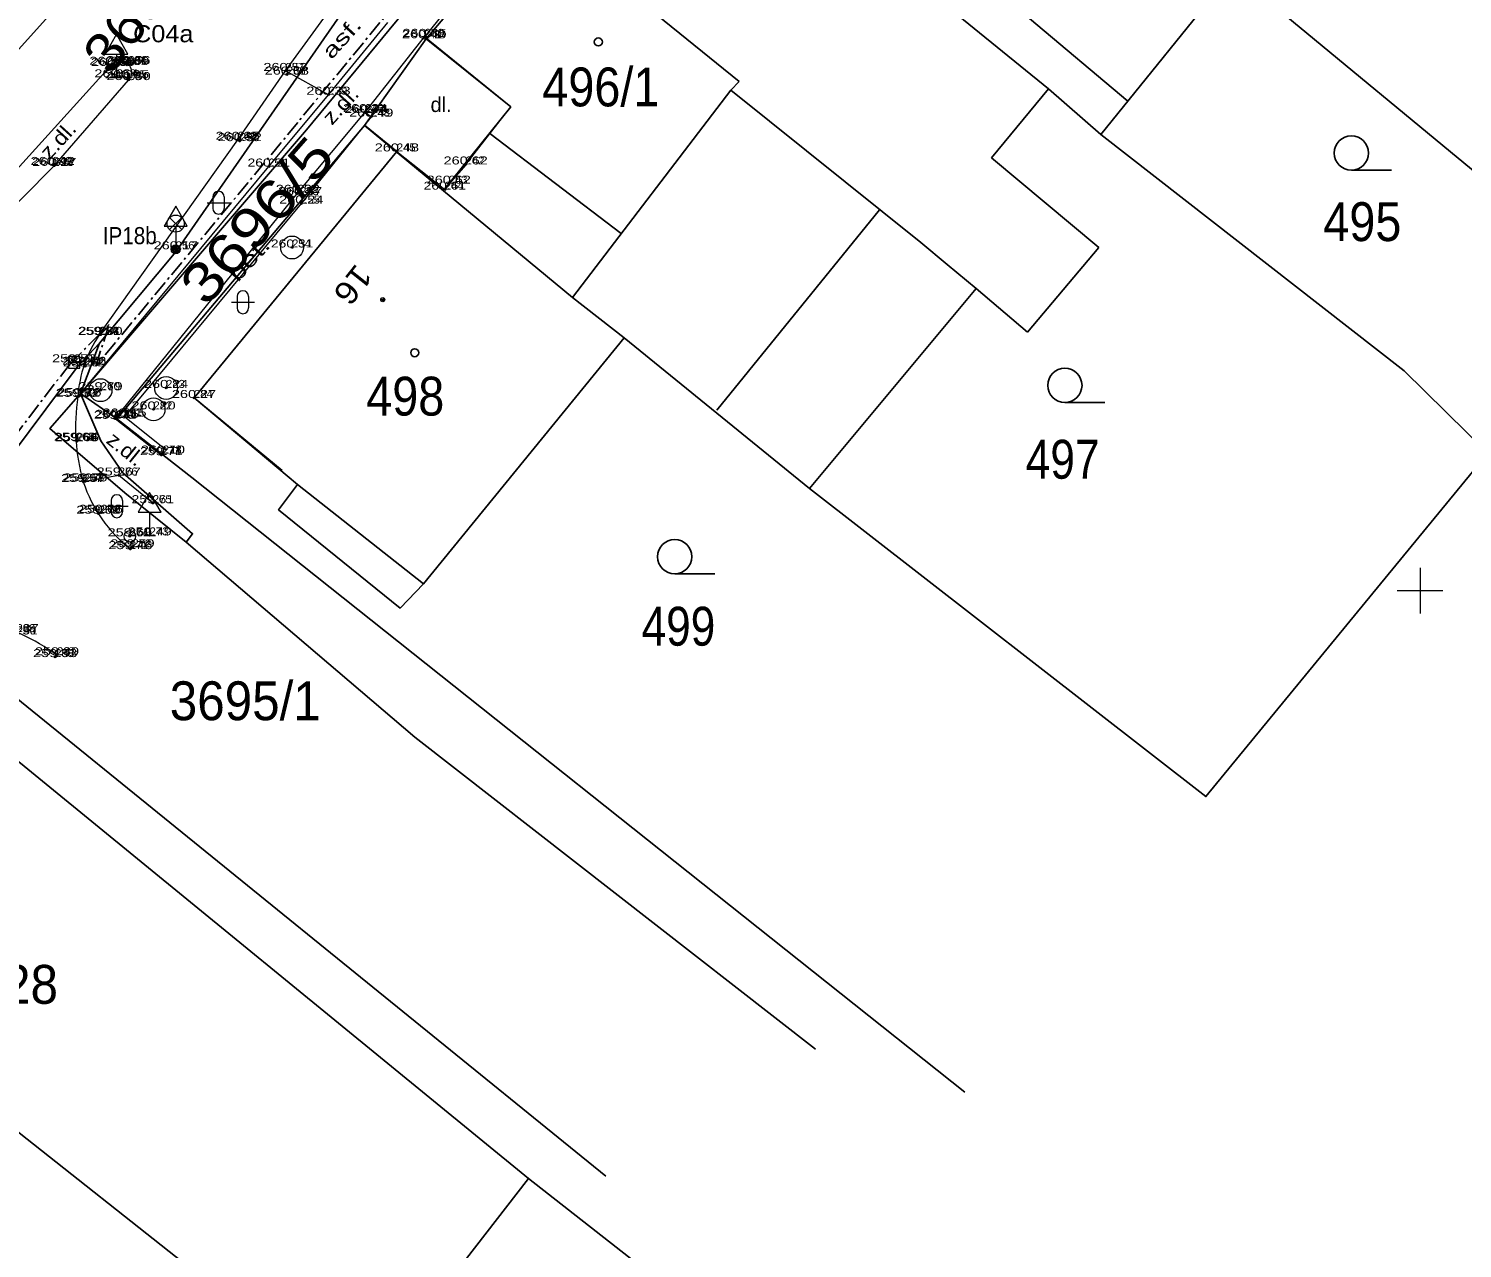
# Model space of a CAD drawing. Extents: x -568530 to -568223, y -1154101 to -1153740.
# Drawn here: x -568460.8 to -568398.2, y -1154028.8 to -1153975.4 of the extents above; entities that cross this region are included whole.
import ezdxf
from ezdxf.enums import TextEntityAlignment as Align

# ---------------------------------------------------------------- set-up
doc = ezdxf.new("R2010")
doc.units = 0
doc.header["$LTSCALE"] = 0.14
doc.header["$PDMODE"] = 32
doc.header["$PDSIZE"] = 0.07
doc.linetypes.add('DOT_DASHED', pattern=[7.7, 5, -1.2, 0.3, -1.2])
for name, color, linetype, lineweight in [('1', 7, 'Continuous', 25), ('10', 7, 'Continuous', 13), ('11', 7, 'Continuous', 13), ('12', 7, 'Continuous', 13), ('25', 7, 'Continuous', 13), ('27', 7, 'Continuous', 13), ('28', 7, 'Continuous', 13), ('33', 7, 'Continuous', 13), ('34', 7, 'Continuous', 13), ('36', 7, 'Continuous', 13), ('39', 7, 'Continuous', 13), ('4', 7, 'Continuous', 25), ('42', 7, 'Continuous', 13), ('5', 7, 'Continuous', 13), ('6', 7, 'DOT_DASHED', 25), ('61', 7, 'Continuous', 13)]:
    doc.layers.add(name, color=color, linetype=linetype, lineweight=lineweight)
for name, color, linetype in [('13', 7, 'Continuous'), ('18', 7, 'Continuous'), ('19', 7, 'Continuous'), ('40', 7, 'Continuous'), ('47', 7, 'Continuous')]:
    doc.layers.add(name, color=color, linetype=linetype)

msp = doc.modelspace()

# ---------------------------------------------------------------- linework, layer by layer
at = {"layer": '1'}
for p, q in [((-568443.46, -1153975.87), (-568433.42, -1153964.08)), ((-568438.82, -1153970.42), (-568429.77, -1153977.74)), ((-568408.2, -1153972.93), (-568390.78, -1153987.34)), ((-568418.74, -1153981.08), (-568416.24, -1153978.06)), ((-568413.96, -1153980.06), (-568400.7, -1153990.39)), ((-568414.04, -1153985), (-568418.74, -1153981.08)), ((-568421.83, -1153984.78), (-568420.68, -1153985.74)), ((-568417.17, -1153988.7), (-568414.04, -1153985)), ((-568420.68, -1153985.74), (-568419.41, -1153986.8)), ((-568419.41, -1153986.8), (-568417.17, -1153988.7)), ((-568457.74, -1153989.19), (-568458.68, -1153990.17)), ((-568457.74, -1153989.19), (-568458.57, -1153991.38)), ((-568458.68, -1153990.17), (-568467.98, -1154002.62)), ((-568465.85, -1154003.75), (-568438.98, -1154025.71)), ((-568474.11, -1154013.58), (-568446.48, -1154035.38))]:
    msp.add_line(p, q, dxfattribs=at)
for points in [[(-568416.35, -1153942.92), (-568421.22, -1153939.56), (-568427.43, -1153948.41), (-568440.04, -1153964.5), (-568454.41, -1153985.19), (-568457.74, -1153989.19)], [(-568421.83, -1153950.13), (-568427.7, -1153957.09), (-568433.42, -1153964.08), (-568426, -1153970.14), (-568416.24, -1153978.06), (-568413.96, -1153980.06), (-568408.2, -1153972.93), (-568413.31, -1153968.6), (-568420.22, -1153963.08), (-568427.7, -1153957.09)], [(-568436.57, -1153965.56), (-568442.92, -1153972.86), (-568448.69, -1153979.85), (-568458.57, -1153991.38), (-568456.99, -1153992.49)], [(-568419.41, -1153986.8), (-568426.69, -1153995.54), (-568434.8, -1153988.95), (-568437.06, -1153987.18), (-568446.16, -1153979.66), (-568443.46, -1153975.87)], [(-568429.77, -1153977.74), (-568430.14, -1153978.12), (-568421.83, -1153984.78)], [(-568446.16, -1153979.66), (-568456.99, -1153992.49), (-568453.71, -1153995.05), (-568419.9, -1154021.94)], [(-568449.08, -1153995.36), (-568453.61, -1153991.58), (-568444.74, -1153980.8)], [(-568449.08, -1153995.36), (-568449.91, -1153996.47), (-568444.59, -1154000.77), (-568443.57, -1153999.71), (-568434.8, -1153988.95)], [(-568426.69, -1153995.54), (-568409.36, -1154009.01), (-568397.04, -1153994), (-568400.7, -1153990.39)], [(-568458.52, -1154050.91), (-568438.98, -1154025.71), (-568434.27, -1154029.4)]]:
    msp.add_lwpolyline(points, dxfattribs=at)
at = {"layer": '10'}
for p, q in [((-568468.5, -1153984.3), (-568459.56, -1153974.44)), ((-568464.54, -1153985.09), (-568457.22, -1153977.01)), ((-568457.75, -1153988.82), (-568451.7, -1153980.29))]:
    msp.add_line(p, q, dxfattribs=at)
for points in [[(-568451.7, -1153980.29), (-568449.61, -1153977.28), (-568446.84, -1153973.45), (-568445.91, -1153972.15), (-568442.46, -1153967.27), (-568439.57, -1153963.38), (-568433.28, -1153955), (-568432.53, -1153954), (-568431.81, -1153953.03), (-568426.84, -1153946.5), (-568420.35, -1153937.98), (-568416.07, -1153932.32)], [(-568463.95, -1153985.68), (-568459.72, -1153981.43), (-568456.47, -1153977.68)]]:
    msp.add_lwpolyline(points, dxfattribs=at)
for centre, radius, start, end in [((-568456.8362, -1153977.3352), 0.503, 316.72145, 139.7276), ((-568453.3107, -1153991.8779), 5.3906, 145.44041, 176.30001), ((-568450.1568, -1153992.8472), 8.6342, 171.22484, 196.15793), ((-568452.5171, -1153993.2846), 6.25, 198.32832, 231.70802), ((-568464.9881, -1154010.2166), 9.1429, 53.8913, 76.66924)]:
    msp.add_arc(centre, radius, start, end, dxfattribs=at)
at = {"layer": '11'}
for p, q in [((-568446.13, -1153979.08), (-568443.53, -1153975.79)), ((-568447.73, -1153978.32), (-568449.61, -1153977.28)), ((-568444.74, -1153980.8), (-568446.162, -1153979.655))]:
    msp.add_line(p, q, dxfattribs=at)
for points in [[(-568458.69, -1153991.53), (-568450.34, -1153981.46), (-568447.73, -1153978.32), (-568445.13, -1153975.16)], [(-568455.04, -1153994.08), (-568457.06, -1153992.49), (-568449.07, -1153982.61), (-568446.13, -1153979.08), (-568445.86, -1153979.28)], [(-568445.86, -1153979.28), (-568446.162, -1153979.655), (-568448.92, -1153983.08)], [(-568448.92, -1153983.08), (-568456.65, -1153992.39), (-568454.82, -1153993.866)], [(-568455.41, -1153996.18), (-568456.9, -1153994.97), (-568458.45, -1153995.25)]]:
    msp.add_lwpolyline(points, dxfattribs=at)
for p in [(-568443.55, -1153975.85), (-568443.53, -1153975.79), (-568457.22, -1153977.01), (-568456.53, -1153977.02), (-568456.48, -1153976.98), (-568457.15, -1153977.06), (-568457, -1153977.56), (-568456.54, -1153977.6), (-568449.61, -1153977.28), (-568449.55, -1153977.44), (-568456.47, -1153977.68), (-568447.73, -1153978.32), (-568446.13, -1153979.08), (-568446.08, -1153979.12), (-568445.86, -1153979.28), (-568451.7, -1153980.29), (-568451.61, -1153980.35), (-568459.79, -1153981.39), (-568444.74, -1153980.8), (-568441.73, -1153981.37), (-568459.72, -1153981.43), (-568450.34, -1153981.46), (-568449.07, -1153982.61), (-568442.64, -1153982.47), (-568442.47, -1153982.21), (-568448.97, -1153982.71), (-568448.92, -1153983.08), (-568454.41, -1153985.08), (-568449.32, -1153985), (-568457.75, -1153988.82), (-568457.7, -1153988.82), (-568458.85, -1153990.02), (-568458.41, -1153990.13), (-568458.37, -1153990.2), (-568457.7, -1153991.24), (-568454.83, -1153991.14), (-568458.69, -1153991.53), (-568458.62, -1153991.5), (-568453.61, -1153991.58), (-568457.06, -1153992.49), (-568456.98, -1153992.45), (-568456.65, -1153992.39), (-568455.38, -1153992.08), (-568458.77, -1153993.45), (-568458.73, -1153993.47), (-568455.04, -1153994.08), (-568454.97, -1153994.01), (-568456.9, -1153994.97), (-568458.45, -1153995.25), (-568458.36, -1153995.23), (-568455.41, -1153996.18), (-568457.79, -1153996.64), (-568457.68, -1153996.6), (-568456.42, -1153997.63), (-568455.55, -1153997.59), (-568456.39, -1153998.19), (-568456.3, -1153998.11), (-568459.68, -1154002.91), (-568459.6, -1154002.83)]:
    msp.add_point(p, dxfattribs=at)
at = {"layer": '25', "lineweight": 25}
for p, q in [((-568403, -1153981.62), (-568401.25, -1153981.62)), ((-568415.53, -1153991.78), (-568413.78, -1153991.78)), ((-568432.59, -1153999.27), (-568430.84, -1153999.27))]:
    msp.add_line(p, q, dxfattribs=at)
for centre, radius in [((-568435.93, -1153976.01), 0.175), ((-568403, -1153980.87), 0.75), ((-568443.96, -1153989.6), 0.175), ((-568415.53, -1153991.03), 0.75), ((-568432.59, -1153998.52), 0.75)]:
    msp.add_circle(centre, radius, dxfattribs=at)
at = {"layer": '27'}
msp.add_line((-568459.1, -1153990.02), (-568458.6, -1153990.02), dxfattribs=at)
msp.add_lwpolyline([(-568459.1, -1153990.27), (-568458.6, -1153990.27), (-568458.6, -1153989.77), (-568459.1, -1153989.77)], close=True, dxfattribs=at)
for centre in [(-568449.32, -1153985), (-568457.7, -1153991.24), (-568454.83, -1153991.14), (-568455.38, -1153992.08)]:
    msp.add_circle(centre, 0.5, dxfattribs=at)
at = {"layer": '28'}
msp.add_circle((-568456.42, -1153997.63), 0.25, dxfattribs=at)
at = {"layer": '33'}
for p, q in [((-568454.675, -1153984.22), (-568454.145, -1153983.69)), ((-568454.675, -1153983.69), (-568454.145, -1153984.22)), ((-568454.41, -1153984.33), (-568454.41, -1153985.08))]:
    msp.add_line(p, q, dxfattribs=at)
for centre, radius in [((-568454.41, -1153983.955), 0.375), ((-568454.41, -1153985.08), 0.2), ((-568454.41, -1153985.08), 0.1445), ((-568454.41, -1153985.08), 0.0876)]:
    msp.add_circle(centre, radius, dxfattribs=at)
at = {"layer": '34'}
for p, q in [((-568457, -1153976.542), (-568457, -1153977.56)), ((-568457.25, -1153977.56), (-568456.75, -1153977.56)), ((-568454.41, -1153984.062), (-568454.41, -1153985.08)), ((-568455.55, -1153996.572), (-568455.55, -1153997.59)), ((-568455.8, -1153997.59), (-568455.3, -1153997.59))]:
    msp.add_line(p, q, dxfattribs=at)
for points in [[(-568457.5, -1153976.542), (-568456.5, -1153976.542), (-568457, -1153975.676)], [(-568454.91, -1153984.062), (-568453.91, -1153984.062), (-568454.41, -1153983.196)], [(-568456.05, -1153996.572), (-568455.05, -1153996.572), (-568455.55, -1153995.706)]]:
    msp.add_lwpolyline(points, close=True, dxfattribs=at)
at = {"layer": '36'}
for p, q in [((-568453.039, -1153983.04), (-568452.039, -1153983.04)), ((-568452.789, -1153982.79), (-568452.789, -1153983.29)), ((-568452.289, -1153982.79), (-568452.289, -1153983.29)), ((-568451.971, -1153987.394), (-568450.971, -1153987.394)), ((-568451.721, -1153987.144), (-568451.721, -1153987.644)), ((-568451.221, -1153987.144), (-568451.221, -1153987.644)), ((-568457.487, -1153996.313), (-568456.487, -1153996.313)), ((-568457.237, -1153996.063), (-568457.237, -1153996.563)), ((-568456.737, -1153996.063), (-568456.737, -1153996.563))]:
    msp.add_line(p, q, dxfattribs=at)
for centre, start, end in [((-568452.5384, -1153982.7905), 0, 180), ((-568452.5384, -1153983.2905), 180, 0), ((-568451.4705, -1153987.1447), 0, 180), ((-568451.4705, -1153987.6447), 180, 0), ((-568456.9863, -1153996.0637), 0, 180), ((-568456.9863, -1153996.5637), 180, 0)]:
    msp.add_arc(centre, 0.25, start, end, dxfattribs=at)
at = {"layer": '39'}
for radius in [0.09, 0.0398]:
    msp.add_circle((-568445.3578, -1153987.2827), radius, dxfattribs=at)
at = {"layer": '4'}
for p, q in [((-568437.06, -1153987.18), (-568430.14, -1153978.12)), ((-568440.68, -1153980.02), (-568434.93, -1153984.39)), ((-568430.75, -1153992.12), (-568423.64, -1153983.36)), ((-568457.68, -1153993.46), (-568458.57, -1153991.38)), ((-568443.57, -1153999.71), (-568449.08, -1153995.36)), ((-568453.95, -1153997.88), (-568443.95, -1154006.41)), ((-568462.84, -1154003.52), (-568435.6, -1154025.6)), ((-568443.95, -1154006.41), (-568426.44, -1154020.05))]:
    msp.add_line(p, q, dxfattribs=at)
for points in [[(-568424.44, -1153968.23), (-568416.69, -1153974.53), (-568417.07, -1153974.98), (-568412.78, -1153978.6)], [(-568443.46, -1153975.87), (-568439.76, -1153978.85), (-568442.71, -1153982.52)], [(-568453.95, -1153997.88), (-568456.63, -1153995.73), (-568459.92, -1153992.91), (-568458.57, -1153991.38)], [(-568453.95, -1153997.88), (-568453.67, -1153997.52), (-568456.72, -1153994.86), (-568457.68, -1153993.46)]]:
    msp.add_lwpolyline(points, dxfattribs=at)
at = {"layer": '5'}
for p, q in [((-568438.92, -1153970.1), (-568443.53, -1153975.79)), ((-568449.749, -1153994.757), (-568453.61, -1153991.58))]:
    msp.add_line(p, q, dxfattribs=at)
for points in [[(-568442.47, -1153982.21), (-568441.73, -1153981.37), (-568439.758, -1153978.846), (-568443.53, -1153975.79)], [(-568453.61, -1153991.58), (-568444.74, -1153980.8), (-568442.64, -1153982.47), (-568442.47, -1153982.21)]]:
    msp.add_lwpolyline(points, dxfattribs=at)
at = {"layer": '6'}
for p, q in [((-568443.31, -1153972.54), (-568449.08, -1153979.53)), ((-568449.07, -1153979.53), (-568457.91, -1153990.19)), ((-568459.03, -1153990.08), (-568457.32, -1153988.37)), ((-568457.91, -1153990.19), (-568457.32, -1153988.37)), ((-568459.03, -1153990.08), (-568468.38, -1154002.32))]:
    msp.add_line(p, q, dxfattribs=at)
at = {"layer": '6', "linetype": 'Continuous', "lineweight": 35}
msp.add_line((-568441.73, -1153981.37), (-568442.47, -1153982.21), dxfattribs=at)
at = {"layer": '61'}
for p, q in [((-568400, -1153999), (-568400, -1154001)), ((-568400, -1153999), (-568400, -1154001)), ((-568401, -1154000), (-568399, -1154000)), ((-568401, -1154000), (-568399, -1154000))]:
    msp.add_line(p, q, dxfattribs=at)

# ---------------------------------------------------------------- texts
at = {"layer": '12'}
for s, width, p in [('260.48', 1.35, (-568443.55, -1153975.85)), ('260.35', 1.35, (-568443.5305, -1153975.79)), ('260.55', 1.35, (-568457.2205, -1153977.01)), ('260.69', 1.35, (-568457.15, -1153977.06)), ('260.69', 1.35, (-568456.53, -1153977.02)), ('260.56', 1.35, (-568456.48, -1153976.98)), ('260.53', 1.35, (-568449.61, -1153977.28)), ('260.64', 1.35, (-568457, -1153977.56)), ('260.65', 1.35, (-568456.5405, -1153977.6)), ('260.50', 1.35, (-568456.4695, -1153977.68)), ('260.68', 1.35, (-568449.55, -1153977.44)), ('260.33', 1.35, (-568447.73, -1153978.32)), ('260.34', 1.35, (-568446.13, -1153979.08)), ('260.74', 1.35, (-568446.08, -1153979.12)), ('260.49', 1.35, (-568445.86, -1153979.28)), ('260.35', 1.35, (-568451.7005, -1153980.29)), ('260.52', 1.35, (-568451.61, -1153980.35)), ('260.48', 1.35, (-568444.74, -1153980.8)), ('260.42', 1.35, (-568459.79, -1153981.39)), ('260.27', 1.35, (-568459.72, -1153981.43)), ('260.21', 1.3, (-568450.34, -1153981.46)), ('260.62', 1.35, (-568441.73, -1153981.37)), ('260.62', 1.35, (-568442.47, -1153982.21)), ('260.22', 1.35, (-568449.07, -1153982.61)), ('260.57', 1.35, (-568448.97, -1153982.71)), ('260.61', 1.3, (-568442.64, -1153982.47)), ('260.24', 1.35, (-568448.92, -1153983.08)), ('260.17', 1.35, (-568454.41, -1153985.08)), ('260.31', 1.3, (-568449.32, -1153985)), ('259.81', 1.3, (-568457.75, -1153988.82)), ('259.90', 1.35, (-568457.6995, -1153988.82)), ('259.73', 1.35, (-568458.85, -1153990.02)), ('259.76', 1.35, (-568458.41, -1153990.13)), ('259.84', 1.35, (-568458.37, -1153990.2)), ('259.72', 1.35, (-568458.69, -1153991.53)), ('259.76', 1.35, (-568458.62, -1153991.5)), ('259.79', 1.35, (-568457.7, -1153991.24)), ('260.24', 1.35, (-568454.83, -1153991.14)), ('260.27', 1.35, (-568453.61, -1153991.58)), ('260.20', 1.35, (-568455.3795, -1153992.08)), ('259.71', 1.3, (-568457.06, -1153992.49)), ('260.15', 1.35, (-568456.9805, -1153992.45)), ('260.15', 1.35, (-568456.6505, -1153992.39)), ('259.64', 1.35, (-568458.77, -1153993.45)), ('259.66', 1.35, (-568458.73, -1153993.47)), ('259.71', 1.3, (-568455.04, -1153994.08)), ('260.10', 1.35, (-568454.9695, -1153994.01)), ('259.57', 1.35, (-568458.45, -1153995.25)), ('259.70', 1.35, (-568458.3595, -1153995.23)), ('259.67', 1.35, (-568456.9, -1153994.97)), ('259.52', 1.35, (-568457.79, -1153996.64)), ('259.66', 1.35, (-568457.68, -1153996.6)), ('259.61', 1.3, (-568455.41, -1153996.18)), ('259.60', 1.35, (-568456.4195, -1153997.63)), ('259.49', 1.35, (-568455.55, -1153997.59)), ('259.46', 1.35, (-568456.39, -1153998.19)), ('259.59', 1.35, (-568456.3, -1153998.11)), ('259.37', 1.35, (-568461.37, -1154001.82)), ('259.51', 1.3, (-568461.37, -1154001.92)), ('259.53', 1.35, (-568459.68, -1154002.91)), ('259.39', 1.35, (-568459.6, -1154002.83))]:
    msp.add_text(s, height=0.35, dxfattribs=dict(at, width=width)).set_placement(p, align=Align.CENTER)
at = {"layer": '13'}
for s, width, p in [('241', 0.95, (-568443.55, -1153975.85)), ('230', 1.1, (-568443.53, -1153975.79)), ('388', 1.05, (-568457.22, -1153977.01)), ('389', 1.05, (-568457.15, -1153977.06)), ('387', 1.05, (-568456.53, -1153977.02)), ('386', 1.05, (-568456.48, -1153976.98)), ('237', 1.05, (-568449.61, -1153977.28)), ('390', 1.1, (-568457, -1153977.56)), ('385', 1.05, (-568456.54, -1153977.6)), ('384', 1.05, (-568456.47, -1153977.68)), ('238', 1.05, (-568449.55, -1153977.44)), ('239', 1.05, (-568447.73, -1153978.32)), ('246', 1.05, (-568446.13, -1153979.08)), ('247', 1.05, (-568446.08, -1153979.12)), ('248', 1.05, (-568445.86, -1153979.28)), ('249', 1.05, (-568451.7, -1153980.29)), ('250', 1.1, (-568451.61, -1153980.35)), ('245', 1.05, (-568444.74, -1153980.8)), ('399', 1.05, (-568459.79, -1153981.39)), ('398', 1.05, (-568459.72, -1153981.43)), ('251', 0.95, (-568450.34, -1153981.46)), ('242', 1.05, (-568441.73, -1153981.37)), ('243', 1.05, (-568442.47, -1153982.21)), ('252', 1.05, (-568449.07, -1153982.61)), ('253', 1.05, (-568448.97, -1153982.71)), ('244', 1.05, (-568442.64, -1153982.47)), ('255', 1.05, (-568448.92, -1153983.08)), ('256', 1.05, (-568454.41, -1153985.08)), ('254', 1.05, (-568449.32, -1153985)), ('257', 1.05, (-568457.75, -1153988.82)), ('258', 1.05, (-568457.7, -1153988.82)), ('259', 1.05, (-568458.85, -1153990.02)), ('262', 1.05, (-568458.37, -1153990.2)), ('263', 1.05, (-568458.69, -1153991.53)), ('264', 1.05, (-568458.62, -1153991.5)), ('260', 1.1, (-568457.7, -1153991.24)), ('283', 1.05, (-568454.83, -1153991.14)), ('284', 1.05, (-568453.61, -1153991.58)), ('282', 1.05, (-568455.38, -1153992.08)), ('279', 1.05, (-568457.06, -1153992.49)), ('280', 1.1, (-568456.98, -1153992.45)), ('281', 0.95, (-568456.65, -1153992.39)), ('265', 1.05, (-568458.77, -1153993.45)), ('266', 1.1, (-568458.73, -1153993.47)), ('277', 1.05, (-568455.04, -1153994.08)), ('278', 1.05, (-568454.97, -1153994.01)), ('267', 1.05, (-568458.45, -1153995.25)), ('268', 1.05, (-568458.36, -1153995.23)), ('276', 1.05, (-568456.9, -1153994.97)), ('269', 1.1, (-568457.79, -1153996.64)), ('270', 1.1, (-568457.68, -1153996.6)), ('275', 1.05, (-568455.41, -1153996.18)), ('274', 1.05, (-568456.42, -1153997.63)), ('273', 1.05, (-568455.55, -1153997.59)), ('271', 0.95, (-568456.39, -1153998.19)), ('272', 1.05, (-568456.3, -1153998.11)), ('289', 1.05, (-568461.37, -1154001.82)), ('290', 1.1, (-568461.37, -1154001.92)), ('288', 1.05, (-568459.68, -1154002.91)), ('287', 1.05, (-568459.6, -1154002.83))]:
    msp.add_text(s, height=0.35, dxfattribs=dict(at, width=width)).set_placement(p)
msp.add_text('261', height=0.35, dxfattribs=at).set_placement((-568458.41, -1153990.13))
at = {"layer": '18'}
for s, rotation, width, p in [('3696/1', 52.5, 1.1, (-568457.236, -1153977.51)), ('3696/5', 48.8, 1.25, (-568453.078, -1153987.638))]:
    msp.add_text(s, height=1.7, rotation=rotation, dxfattribs=dict(at, width=width)).set_placement(p)
for s, width, p in [('495', 0.9, (-568404.23, -1153984.72)), ('497', 0.85, (-568417.24, -1153995.11)), ('499', 0.85, (-568434.04, -1154002.41)), ('3695/1', 0.95, (-568454.67, -1154005.67)), ('528', 0.95, (-568463.16, -1154018.07))]:
    msp.add_text(s, height=1.7, dxfattribs=dict(at, width=width)).set_placement(p)
at = {"layer": '19', "width": 0.9}
for s, p in [('496/1', (-568438.38, -1153978.83)), ('498', (-568446.08, -1153992.35))]:
    msp.add_text(s, height=1.7, dxfattribs=at).set_placement(p)
at = {"layer": '40'}
for s, rotation, width, p in [('asf.', 47.739, 1.45, (-568447.599, -1153976.811)), ('z.dl.', 47.739, 1.15, (-568447.578, -1153979.684)), ('z.dl.', 47.739, 1.15, (-568459.934, -1153981.203)), ('bet.', 47.739, 1.5, (-568451.689, -1153986.549)), ('z.dl.', 321.052, 1.1, (-568457.492, -1153993.512))]:
    msp.add_text(s, height=0.65, rotation=rotation, dxfattribs=dict(at, width=width)).set_placement(p)
msp.add_text('dl.', height=0.65, dxfattribs=at).set_placement((-568443.266, -1153979.076))
at = {"layer": '42'}
for s, width, p in [('C04a', 1.1, (-568454.9535, -1153976.027)), ('IP18b', 0.9, (-568456.42, -1153984.857))]:
    msp.add_text(s, height=0.75, dxfattribs=dict(at, width=width)).set_placement(p, align=Align.CENTER)
at = {"layer": '47', "width": 1.15}
msp.add_text('16', height=1, rotation=231.636, dxfattribs=at).set_placement((-568446.512, -1153985.656))

doc.saveas('drawing.dxf')
